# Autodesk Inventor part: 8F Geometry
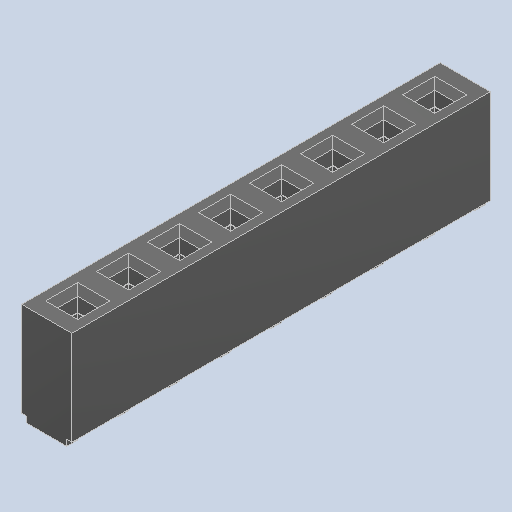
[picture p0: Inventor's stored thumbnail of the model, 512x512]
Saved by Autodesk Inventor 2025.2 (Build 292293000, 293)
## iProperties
Created: 2025-04
Part Number: 8F Geometry
Material: Generic
Description: PART-8F Geometry-DESC
Document SubType Name: Modeling
Designer: BennF
Density: 1 g/cm^3
Appearance: Default
Author: BennF
Revision Number: NONE
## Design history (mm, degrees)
feature "Solid"
body "Solid1"
